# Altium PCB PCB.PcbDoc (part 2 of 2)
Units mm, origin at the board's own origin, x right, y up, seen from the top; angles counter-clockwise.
Board outline 43.18 x 17.78 mm, 4 copper layers (TOP, GND, SIG, BOTTOM), stack 1.586 mm thick; 72 components, 65 nets, 299 pads, 183 vias.
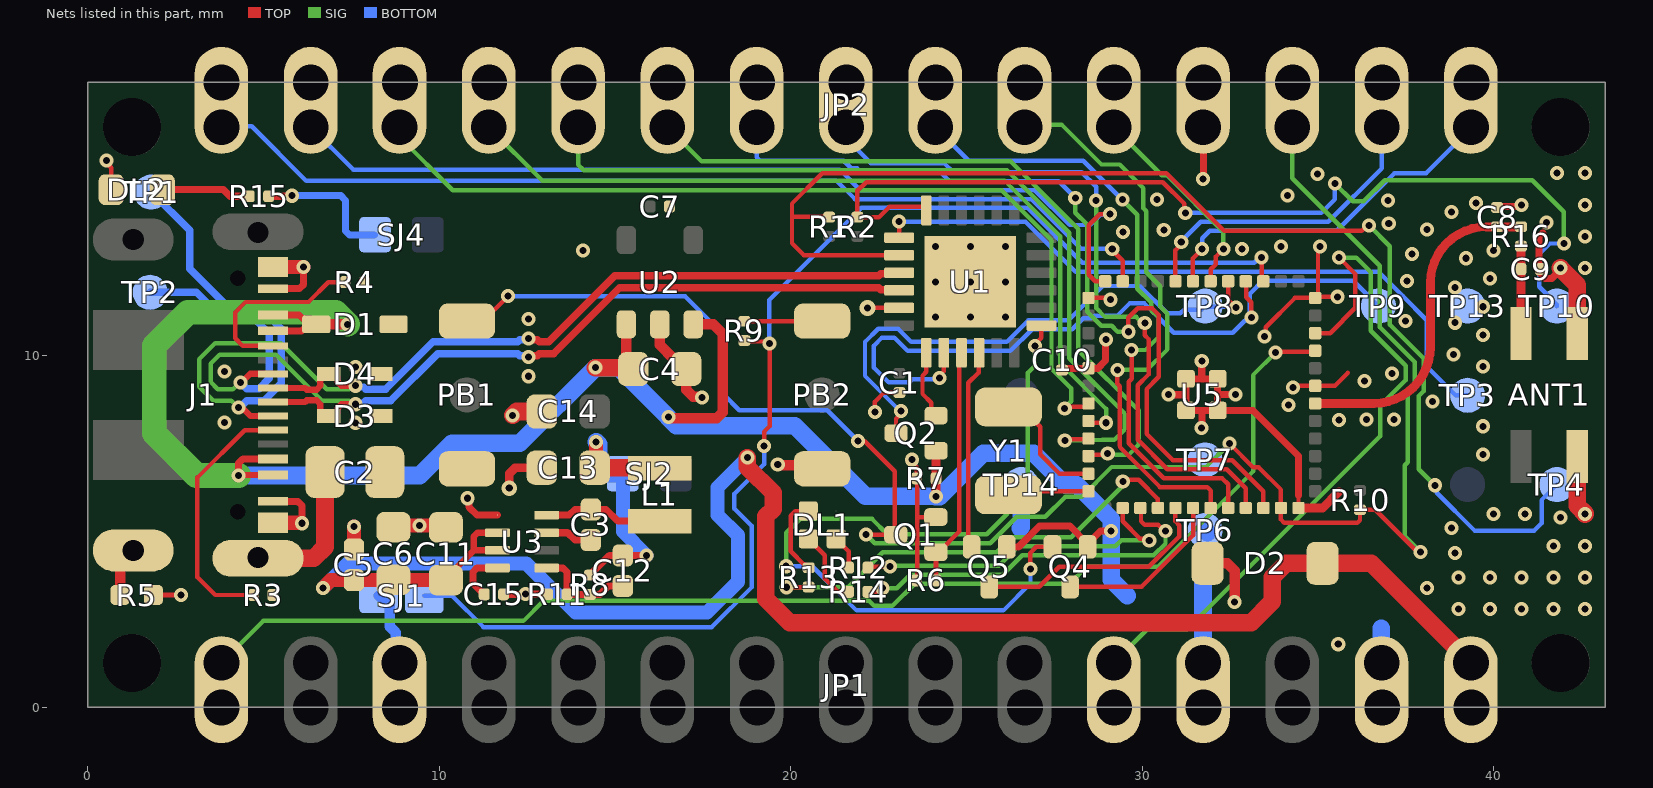
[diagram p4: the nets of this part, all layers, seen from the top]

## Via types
v1: diameter 0.4, hole 0.2, TOP to BOTTOM, tented both sides, 172 vias
v2: diameter 0.45, hole 0.2, TOP to BOTTOM, tented both sides, 11 vias

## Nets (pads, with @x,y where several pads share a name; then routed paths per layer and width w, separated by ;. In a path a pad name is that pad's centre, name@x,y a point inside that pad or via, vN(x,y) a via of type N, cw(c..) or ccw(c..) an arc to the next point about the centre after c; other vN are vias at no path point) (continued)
A7: JP1.11 U5.10 | length 19.8
  TOP w0.127: U5.10@34.925,10.65 35.35,10.65 36.068,11.368 36.068,12.332 v1(35.6,12.8)
  SIG w0.127: JP1.11@29.195,1.27 30.151,2.226 31.279,2.226 36.776,7.723 36.776,8.59 37.501,9.314 37.501,9.724 36.507,10.717 36.507,12.388 36.095,12.8 v1(35.6,12.8)
AREF_5: JP1.3 SJ1.1 | length 2.2
  BOTTOM w0.3: SJ1.1@8.28,3.182 8.598,2.864 8.598,2.305 8.77,2.132 8.77,1.375 JP1.3@8.875,1.27
CC1_3: J1.A5 R4.2 | length 5.4
  TOP w0.127: J1.A5@5.276,10.29 4.41,10.29 4.2,10.5 4.2,11.238 4.497,11.535 6.288,11.535 6.853,12.1 R4.2@7.333,12.1
CC2_3: J1.B5 R3.2 | length 7.4
  TOP w0.127: R3.2@4.725,3.2 3.635,3.2 3.126,3.709 3.126,6.545 4.472,7.89 J1.B5@5.276,7.89
CLK: JP1.1 U5.9 | length 36.5
  TOP w0.127: v1(33.8,10.1) 33.825,10.125 34.9,10.125 U5.9@34.925,10.15
  SIG w0.127: JP1.1@3.81,1.27 5.003,2.463 12.401,2.463 12.968,3.03 22.24,3.03 22.382,2.888 22.897,2.888 23.533,3.524 27.946,3.524 28.432,4.009 30.453,4.009 33.157,6.714 33.157,9.457 v1(33.8,10.1)
D2_SWV: JP2.5 U5.18 | length 5.9
  TOP w0.127: U5.18@31.953,12.127 31.953,12.463 32.102,12.612 32.102,12.83 32.312,13.04 v1(32.312,13.044)
  SIG w0.127: JP2.5@29.195,16.51 30.563,15.142 30.708,15.142 32.312,13.538 v1(32.312,13.044)
D3: JP2.6 U5.43 | length 16.5
  TOP w0.127: v1(29.3,9.605) 29.3,9.208 29.366,9.143 29.366,7.441 29.373,7.434 29.373,7.406 30.508,6.27 31.852,6.27 31.95,6.172 U5.43@31.95,5.675
  SIG w0.127: JP2.6@26.655,16.51 26.719,16.573 27.72,16.573 28.846,15.447 29.364,15.447 30.04,14.771 30.04,14.202 30.121,14.121 30.121,12.379 30.515,11.985 30.515,11.408 30.722,11.202 30.722,10.186 30.14,9.605 v1(29.3,9.605)
D4: JP2.7 U5.44 | length 18.1
  TOP w0.127: v1(29.705,10.17) 29.705,9.352 29.622,9.269 29.622,7.516 30.613,6.524 31.841,6.524 32.276,6.524 32.45,6.35 U5.44@32.45,5.675
  SIG w0.127: v1(29.437,14.445) 29.867,14.016 29.867,11.916 30.261,11.522 30.261,11.303 30.468,11.096 30.468,10.54 30.098,10.17 v1(29.705,10.17)
  BOTTOM w0.127: JP2.7@24.115,16.51 25.068,15.557 28.325,15.557 v1(29.437,14.445)
D5: JP2.8 U5.45 | length 20.7
  TOP w0.127: v1(30.077,10.935) 30.077,10.588 30.184,10.481 30.184,9.473 29.876,9.164 29.876,7.621 30.719,6.778 32.411,6.778 32.95,6.239 U5.45@32.95,5.675
  SIG w0.127: v1(28.693,14.418) 28.692,13.845 28.694,13.844 28.694,11.363 28.946,11.111 29.829,11.111 30.005,10.935 v1(30.077,10.935)
  BOTTOM w0.127: JP2.8@21.575,16.51 21.575,16.195 22.282,15.488 24.364,15.488 24.625,15.227 28.278,15.227 28.693,14.812 v1(28.693,14.418)
D6: JP2.9 U5.46 | length 24.6
  TOP w0.127: v1(29.611,10.689) 29.611,11.09 29.879,11.358 30.284,11.358 30.476,11.166 30.476,9.405 30.13,9.059 30.13,7.781 30.879,7.032 32.566,7.032 33.45,6.148 U5.46@33.45,5.675
  SIG w0.127: v1(28.1,14.5) 28.101,14.077 28.44,13.739 28.44,11.258 28.841,10.857 29.134,10.857 29.302,10.689 v1(29.611,10.689)
  BOTTOM w0.127: JP2.9@19.035,16.51 19.035,15.648 19.126,15.557 21.507,15.557 21.723,15.342 21.891,15.342 21.999,15.234 24.259,15.234 24.52,14.973 27.627,14.973 v1(28.1,14.5)
D7: JP2.10 U5.34 | length 21.3
  TOP w0.127: U5.34@28.475,7.15 28.516,7.19 28.983,7.19 v1(29.023,7.231)
  SIG w0.127: JP2.10@16.495,16.51 17.471,15.534 26.263,15.534 28.186,13.611 28.186,10.167 29.9,8.452 29.9,7.472 29.613,7.186 29.069,7.186 v1(29.023,7.231)
D8: JP2.11 U5.33 | length 24.7
  TOP w0.127: v1(27.801,7.601) 27.826,7.626 28.4,7.626 28.425,7.6 U5.33@28.475,7.65
  SIG w0.127: JP2.11@13.955,16.51 13.955,15.439 14.114,15.28 26.158,15.28 27.932,13.506 27.932,9.937 29.5,8.368 29.5,7.9 29.21,7.61 29.199,7.61 29.187,7.622 28.864,7.622 28.851,7.61 28.573,7.61 28.563,7.6 27.802,7.6 v1(27.801,7.601)
D_N: D4.2 J1.A7 J1.B7 TP1.X U1.21 | length 37.2
  TOP w0.18: v1@4.35,8.587 4.647,8.29 J1.A7@5.276,8.29 ; J1.B7@5.276,9.09 6.186,9.09 6.233,9.043 6.517,9.043 6.623,9.149 6.623,9.38 6.733,9.49 D4.2@6.868,9.49 7.003,9.49 7.113,9.38 7.113,9.259 7.218,9.153 v1(7.618,9.153)
  TOP w0.213: v1(12.545,10.502) 12.581,10.466 12.788,10.466 12.846,10.408 13.116,10.408 14.994,12.286 22.504,12.286 22.563,12.345 23.067,12.345 U1.21@23.088,12.366
  SIG w0.127: v1(4.3,8.537) 4.284,8.537 4.089,8.731 3.573,8.731 3.176,9.129 3.176,9.913 3.628,10.365 5.493,10.365 6.806,9.052 7.443,9.052 7.544,9.153 v1(7.618,9.153)
  BOTTOM w0.213: TP1.X@1.821,14.66 2.904,13.577 2.904,12.487 3.951,11.44 4.851,11.44 5.511,10.78 5.511,9.22 5.021,8.73 4.529,8.73 4.335,8.537 v1@4.311,8.537 ; v1(7.618,9.153) 7.654,9.118 7.861,9.118 7.919,9.06 8.48,9.06 9.828,10.408 12.245,10.408 12.303,10.466 12.509,10.466 v1(12.545,10.502)
D_P: D3.2 J1.A6 J1.B6 TP2.X U1.22 | length 33.4
  TOP w0.18: v1(4.349,9.25) 4.386,9.25 4.627,9.49 J1.A6@5.276,9.49 ; J1.B6@5.276,8.69 6.186,8.69 6.233,8.737 6.517,8.737 6.623,8.631 6.623,8.4 6.733,8.29 D3.2@6.868,8.29 7.003,8.29 7.113,8.4 7.113,8.521 7.218,8.627 v1(7.618,8.627)
  TOP w0.213: v1(12.545,9.975) 12.581,10.011 12.788,10.011 12.846,10.069 13.257,10.069 15.135,11.946 22.504,11.946 22.563,11.887 23.067,11.887 U1.22@23.088,11.866
  SIG w0.127: v1(4.349,9.25) 4.333,9.25 4.138,9.055 3.708,9.055 3.5,9.263 3.5,9.778 3.763,10.041 5.359,10.041 6.672,8.728 7.443,8.728 7.544,8.627 v1(7.618,8.627)
  BOTTOM w0.213: TP2.X@1.789,11.811 3.1,11.811 3.811,11.1 4.711,11.1 5.171,10.64 5.171,9.36 4.88,9.07 4.529,9.07 v1(4.349,9.25) ; v1(7.618,8.627) 7.654,8.662 7.861,8.662 7.919,8.72 8.62,8.72 9.969,10.069 12.245,10.069 12.303,10.011 12.509,10.011 v1(12.545,9.975)
GND: ANT1.3 ANT1.4 C1.1 C2.1 C4.1 C5.2 C6.1 C7.1 C8.2 C9.2 C10.1 C11.1 C13.1 C14.1 C15.1 D1.2 D3.1 D4.1 DL2.C J1.A1 J1.A12 J1.B1 J1.B12 JP1.14 JP2.4 PB1.1 PB2.1 Q1.S R3.1 R4.1 R5.1 R6.2 R7.2 R11.1 TP13.X TP14.X U1.23 U1.EXP U2.2 U3.1 U5.7 U5.12 U5.25 U5.29 U5.48 U5.49 U5.50 U5.51 U5.52 | length 54.7
  TOP w0.127: v1(0.544,15.563) 0.544,15.49 0.675,15.359 DL2.C@0.675,14.73 ; v2(22.193,11.366) U1.23@23.088,11.366 ; v1(22.4,8.4) 22.4,8.7 22.66,8.96 C1.1@23.097,8.96 ; v1(23.452,7.049) 23.452,6.975 23.588,6.839 R7.2@23.588,6.518 23.601,6.505 23.601,5.418 ; R6.2@23.588,3.618 23.601,3.631 23.601,5.418 ; Q1.S@24.133,5.418 23.601,5.418 ; U5.25@28.475,11.65 29.05,11.65 v1(29.1,11.6) ; v1@33.411,10.551 v1(33.485,10.551) ; v1@33.517,10.583 33.517,10.817 34.35,11.65 U5.12@34.925,11.65 U5.12@34.959,11.684 ; v1(34.3,9.1) 34.35,9.15 U5.7@34.925,9.15 35.489,9.15 35.856,9.517 ; U5.48@34.45,5.675 34.45,6.028 ; v1(35.057,13.111) 35.005,13.059 35.005,11.73 U5.12@34.959,11.684 ; v1(35.56,11.684) U5.12@34.959,11.684 ; v1@40.75,14.25 v1@40.8,14.2
  TOP w0.15: R5.1@1.875,3.2 1.877,3.198 2.663,3.198 v1(2.664,3.197)
  TOP w0.2: J1.B1@5.276,5.865 5.981,5.865 6.098,5.748 v1(6.098,5.241) ; J1.B12@5.276,11.915 6.033,11.915 6.15,12.032 v1(6.15,12.53) ; v1(10.811,5.952) 10.85,5.914 10.85,5.698 11.076,5.471 U3.1@11.663,5.471 ; C15.1@11.835,3.22 12.444,3.22 v1(12.459,3.234) 13.075,3.234 R11.1@13.088,3.221 ; C10.1@27.725,9.6 27.775,9.65 U5.29@28.475,9.65 28.742,9.65 28.958,9.866 28.958,10.451 v1(28.972,10.466)
  TOP w0.203: U1.EXP@24.396,11.385 v2(25.121,12.11) ; v1(30.748,8.899) 31.249,8.899 ; v1(31.69,7.952) 31.701,7.963 31.701,8.449 ; v1(31.699,9.852) 31.699,9.351 31.7,9.35 ; JP2.4@31.735,16.51 31.749,16.496 31.749,15.052 v1(31.738,15.041) ; 32.151,8.901 v1(32.652,8.901) ; 34.45,6.028 34.45,7.154 33.154,8.45 U5.49@32.15,8.45 ; C8.2@40.2,14.25 v1@40.75,14.25 ; 41.4,13.5 41.296,13.396 41.296,12.506 41.297,12.505 41.297,12.371 41.468,12.2 41.658,12.2 41.908,12.45 v1@41.95,12.45 ; 31.7,9.35 U5.52@32.15,9.35 U5.49@32.15,8.45 ; 31.7,9.35 U5.51@31.25,9.35 U5.50@31.25,8.45 U5.49@32.15,8.45
  TOP w0.25: U5.48@34.45,5.675 35.139,5.675 35.6,6.136
  TOP w0.254: v2(11.997,6.239) 11.997,6.653 12.166,6.821 C13.1@12.928,6.821
  TOP w0.3: U2.2@16.28,10.9 16.28,10.314 16.679,9.915 16.75,9.915 17.03,9.635 17.03,9.039 17.231,8.838 17.462,8.838 v1(17.481,8.819) ; v1(19.636,6.914) 19.655,6.895 20.795,6.895 PB2.1@20.9,6.79
  TOP w0.356: v1@6.072,5.255 6.086,5.241 v1(6.098,5.241)
  TOP w0.4: J1.A12@5.276,5.255 v1@6.072,5.255 ; J1.A1@5.28,12.53 v1(6.15,12.53) ; C5.2@7.58,4.542 v1(7.58,5.142) ; C6.1@8.935,5.182 C11.1@10.066,5.182
  TOP w0.5: v1(12.095,8.311) 12.206,8.421 C14.1@12.928,8.421
  TOP w0.508: J1.A1@5.276,12.525 J1.A1@5.28,12.53 ; v1(41.9,12.5) 41.95,12.45 42.38,12.02 ANT1.4@42.38,10.64 ; ANT1.3@42.38,7.14 42.38,5.739 42.6,5.519 v1(42.6,5.5)
  BOTTOM w0.5: 25.625,6.2 25.766,6.341 TP14.X@26.563,6.341 26.563,5.125 26.538,5.1 ; 36.8,2.25 36.8,1.27 JP1.14@36.815,1.27
  other v1: 35.581,1.8 39,2.8 39.9,2.8 40.8,2.8 41.7,2.8 42.6,2.8 38.1,3.4 39,3.7 39.9,3.7 40.8,3.7 41.7,3.7 42.6,3.7 38.9,4.4 41.7,4.6 42.6,4.6 38.8,5.1 9.443,5.182 41.9,5.4 40,5.5 40.9,5.5 39.7,7.2 39.7,8 3.894,8.107 7.618,8.1 35.605,8.184 36.386,8.189 37.167,8.189 34.163,8.607 38.26,8.7 36.331,9.289 12.545,9.423 37.11,9.5 3.894,9.555 7.618,9.68 39.7,9.7 38.86,10.046 39.7,10.6 38.9,10.946 37.499,10.999 12.545,11.055 39.7,11.4 38.9,11.946 37.536,12.136 39.9,12.2 42.6,12.5 39.22,12.78 37.68,12.9 14.1,13 40,13 32.847,13.044 33.947,13.114 42.6,13.4 29.452,13.521 30.618,13.586 38.105,13.595 37.018,13.77 41.5,13.8 38.8,14.1 40.8,14.3 42.6,14.3 39.5,14.35 37,14.421 30.431,14.454 34.134,14.559 34.994,15.179 41.8,15.2 42.6,15.2
  other v2: 24.121,11.11 25.121,11.11 26.121,11.11 24.121,12.11 26.121,12.11 24.121,13.11 25.121,13.11 26.121,13.11
MGM_AREF: R9.2 SJ1.2 U5.15 | length 36.2
  TOP w0.127: R9.2@18.687,10.437 18.712,10.411 19.275,10.411 19.33,10.356 v1(19.404,10.356) 19.404,8.002 19.246,7.844 v1(19.246,7.438) ; v1(33.4,12.8) 33.4,12.175 U5.15@33.45,12.125
  BOTTOM w0.127: SJ1.2@9.58,3.182 10.37,3.182 11.264,2.288 17.762,2.288 18.891,3.416 18.891,5.167 18.404,5.654 18.404,6.08 19.246,6.923 v1(19.246,7.438) ; v1(19.404,10.356) 19.392,10.368 19.392,11.592 22.011,14.211 26.739,14.211 28.297,12.653 33.189,12.653 33.336,12.8 v1(33.4,12.8)
MGM_RESET_CTL_4: Q1.G R6.1 U1.3 | length 6.8
  TOP w0.127: Q1.G@24.133,4.418 24.213,4.418 24.806,5.011 24.806,10.034 U1.3@24.863,10.091
  TOP w0.15: Q1.G@24.133,4.418 24.138,4.413 R6.1@24.138,3.618
MISO: JP2.15 U5.23 | length 27.8
  TOP w0.127: v1(29.152,13.048) 29.152,13.006 29.451,12.708 U5.23@29.451,12.126
  BOTTOM w0.127: JP2.15@3.81,16.51 3.833,16.533 4.672,16.533 6.225,14.98 21.317,14.98 21.833,14.465 26.844,14.465 28.26,13.048 v1(29.152,13.048)
MOSI: JP2.14 U5.24 | length 26.7
  TOP w0.127: U5.24@28.95,12.125 28.671,12.125 28.481,12.314 28.481,13.717 28.796,14.032 29.071,14.032 v1(29.083,14.044)
  BOTTOM w0.127: JP2.14@6.35,16.51 7.557,15.303 21.402,15.303 21.987,14.719 26.949,14.719 27.942,13.726 28.527,13.726 28.815,14.014 29.052,14.014 v1(29.083,14.044)
NetANT1_1: ANT1.1 C9.1 R16.2 | length 2.5
  TOP w0.254: ANT1.1@40.78,10.64 R16.2@40.78,13.105
NetC2_2: C2.2 J1.SHIELD2 | length 4.4
  TOP w0.508: J1.SHIELD2@4.929,4.349 J1.SHIELD2@4.851,4.27 4.876,4.245 6.435,4.245 6.758,4.568 6.758,6.797 C2.2@6.75,6.805
NetC3_1: C3.1 L1.1 U3.8 | length 3.4
  TOP w0.2: U3.8@13.063,5.471 13.699,5.471 13.863,5.635 C3.1@14.318,5.635 14.753,5.635 15.086,5.302 L1.1@16.28,5.302
NetC3_2: C3.2 U3.7 | length 1.3
  TOP w0.2: U3.7@13.063,4.971 13.66,4.971 13.867,4.765 C3.2@14.318,4.765
NetC8_1: C8.1 R16.1 U5.6 | length 9.5
  TOP w0.254: U5.6@34.925,8.65 36.593,8.65 36.594,8.65 ccw(c36.594,10.256) 38.2,10.256 38.2,12.08 cw(c39.795,12.08) 39.795,13.675 R16.1@40.8,13.675
NetC12_1: C12.1 R8.1 R11.2 U3.5 | length 3
  TOP w0.2: U3.5@13.063,3.971 13.521,3.971 13.638,3.854 R11.2@13.638,3.221 14.291,3.221 R8.1@14.297,3.215 ; R8.1@14.322,3.191 R8.1@14.297,3.215 ; C12.1@15.23,3.455 14.813,3.455 14.574,3.215 R8.1@14.297,3.215
NetC12_2: C12.2 C13.2 L1.2 R8.2 SJ2.1 | length 8.5
  TOP w0.2: R8.2@14.297,3.779 14.325,3.779 14.367,3.82 14.367,3.849 14.843,4.325 C12.2@15.23,4.325 v1(15.906,4.325)
  TOP w0.4: C13.2@14.428,6.821 14.468,6.861 v1(14.468,7.553)
  TOP w0.5: C13.2@14.428,6.821 16.26,6.821 L1.2@16.28,6.802
  BOTTOM w0.4: SJ2.1@15.23,6.652 15.23,5.002 v1(15.906,4.325)
  BOTTOM w0.5: v1(14.468,7.553) 14.539,7.483 14.539,6.944 14.832,6.652 SJ2.1@15.23,6.652
NetC15_2: C15.2 U3.4 | length 1.5
  TOP w0.2: C15.2@11.284,3.22 11.284,3.235 11.229,3.29 11.21,3.29 10.967,3.533 10.967,3.858 11.084,3.975 U3.4@11.659,3.975
NetDL1_1: DL1.1 R13.1 | length 2.3
  TOP w0.127: DL1.1@20.505,5.589 20.137,5.589 20.007,5.459 20.007,4.441 20.392,4.056 20.434,4.056 R13.1@20.515,3.975
NetDL1_2: DL1.2 R14.1 | length 2.2
  TOP w0.127: DL1.2@20.505,4.799 20.971,4.333 20.971,3.668 21.35,3.29 R14.1@21.65,3.29
NetDL1_3: DL1.3 R12.1 | length 1
  TOP w0.127: DL1.3@21.295,4.799 21.65,4.444 R12.1@21.65,3.98
NetDL2_A: DL2.A R15.1 | length 2.6
  TOP w0.2: DL2.A@2.125,14.73 3.87,14.73 4.056,14.544 R15.1@4.602,14.544
NetJ1_SHIELD4: J1.SHIELD4 R5.2 | length 1.4
  TOP w0.3: R5.2@0.925,3.2 0.925,4.094 J1.SHIELD4@1.301,4.47
NetPB2_2: PB2.2 R9.1 | length 2.2
  TOP w0.127: R9.1@18.687,10.987 20.897,10.987 PB2.2@20.9,10.99
NetR15_2: R15.2 SJ4.2 | length 4
  TOP w0.2: R15.2@5.152,14.544 5.796,14.544 v1(5.811,14.559)
  BOTTOM w0.2: v1(5.811,14.559) 7.208,14.559 7.341,14.426 7.341,13.556 7.458,13.439 SJ4.2@8.169,13.439
NetU5_35: U5.35 Y1.2 | length 3.6
  TOP w0.127: Y1.2@26.2,8.55 26.626,8.55 26.626,8.463 27.1,7.989 27.1,7.2 27.65,6.65 U5.35@28.475,6.65
NetU5_36: U5.36 Y1.1 | length 2.3
  TOP w0.127: Y1.1@26.2,6.05 26.3,6.15 U5.36@28.475,6.15
PTI_DATA: JP2.12 U5.32 | length 23.9
  TOP w0.127: U5.32@28.475,8.15 28.525,8.1 v1(28.975,8.1)
  SIG w0.127: JP2.12@11.415,16.51 12.935,14.99 26.089,14.99 27.678,13.401 27.678,9.79 28.975,8.493 v1(28.975,8.1)
PTI_SYNC: JP2.13 U5.31 | length 25.9
  TOP w0.127: v1(27.8,8.5) 27.862,8.562 28.387,8.562 U5.31@28.475,8.65
  SIG w0.127: JP2.13@8.875,16.51 8.875,16.23 10.39,14.716 26.004,14.716 27.424,13.296 27.424,9.636 27.984,9.077 27.984,8.711 27.8,8.527 v1(27.8,8.5)
R\E\S\E\T\: JP2.3 PB1.2 Q1.D R10.1 TP7.X U5.47 | length 52.2
  TOP w0.127: PB1.2@10.794,10.99 11.119,11.314 11.576,11.314 v1(11.962,11.7) ; v1(21.922,7.577) 22.113,7.577 22.967,6.723 22.967,4.944 Q1.D@22.993,4.918 22.146,4.918 v1(22.142,4.922) ; v1(32.485,7.509) 33.165,6.828 33.322,6.828 33.95,6.2 U5.47@33.95,5.675 33.95,5.348 34.048,5.25 36.126,5.25 36.2,5.324 R10.1@36.2,5.625 36.631,5.625 37.712,4.544 37.718,4.544 37.838,4.423 v1(37.926,4.423)
  SIG w0.127: v1(22.142,4.922) 22.393,4.671 25.68,4.671 26.431,5.422 27.25,5.422 27.818,5.99 28.28,5.99 29.131,6.841 31.818,6.841 v1@32.479,7.502 ; JP2.3@34.275,16.51 34.275,15.052 36.761,12.566 36.761,10.822 37.755,9.829 37.755,9.189 37.557,8.992 37.557,6.976 37.473,6.892 37.473,4.876 v1(37.926,4.423)
  BOTTOM w0.127: v1(11.962,11.7) 17,11.7 18.105,10.595 18.105,8.894 18.542,8.456 21.043,8.456 v1(21.922,7.577) ; TP7.X@31.795,7.041 32.017,7.041 v1(32.485,7.509)
RGB_B: R13.2 U5.40 | length 13
  TOP w0.127: v1(19.879,3.421) 19.882,3.423 20.513,3.423 R13.2@20.515,3.425 ; v1(29.451,6.43) 29.498,6.477 29.905,6.477 30.45,5.932 U5.40@30.45,5.675
  SIG w0.127: v1(19.879,3.421) 19.885,3.416 21.624,3.416 22.626,4.417 25.868,4.417 26.291,4.84 27.985,4.84 29.451,6.306 v1(29.451,6.43)
RGB_G: R14.2 U5.39 | length 10.6
  TOP w0.127: R14.2@22.2,3.29 22.437,3.29 22.541,3.393 v1(22.615,3.393) ; U5.39@29.95,5.675 29.97,5.656 29.97,5.299 30.071,5.197 30.456,5.197 30.628,5.025 v1(30.667,5.025)
  SIG w0.127: v1(22.615,3.393) 23.022,3.393 23.407,3.778 26.036,3.778 26.59,4.332 30.336,4.332 30.667,4.662 v1(30.667,5.025)
RGB_R: R12.2 U5.38 | length 9.7
  TOP w0.127: R12.2@22.2,3.98 22.218,3.997 22.814,3.997 v1(22.831,4.015) ; U5.38@29.45,5.675 29.45,5.295 29.94,4.805 30.152,4.805 v1(30.205,4.752)
  SIG w0.127: v1(22.831,4.015) 22.848,4.032 25.93,4.032 26.485,4.586 29.238,4.586 29.405,4.752 v1(30.205,4.752)
SAMD11_N_RESET_4: R2.2 TP10.X U1.18 | length 28.4
  TOP w0.127: U1.18@23.863,14.141 23.863,14.154 23.777,14.24 22.805,14.24 22.514,13.95 R2.2@21.9,13.95 21.9,14.696 22.15,14.946 30.588,14.946 31.198,14.336 31.198,14.099 v1(31.229,14.068)
  SIG w0.127: v1(35.488,14.903) 35.991,14.4 36.3,14.4 36.9,15 41.1,15 42,14.1 v1(42,13.2)
  BOTTOM w0.127: v1(31.229,14.068) 35.097,14.068 35.488,14.459 v1(35.488,14.903) ; TP10.X@41.803,11.421 41.803,11.464 41.3,11.967 41.3,12.9 41.6,13.2 v1(42,13.2)
SAMD11_PA02_4: Q2.S U1.1 | length 2
  TOP w0.127: U1.1@23.863,10.091 23.863,9.549 23.753,9.439 23.753,8.92 24.002,8.671 24.002,8.44 Q2.S@24.137,8.305
SAMD11_PA05_4: Q5.S U1.4 | length 5.7
  TOP w0.127: Q5.S@25.152,4.571 25.06,4.664 25.06,9.237 25.351,9.529 25.351,10.079 U1.4@25.363,10.091
SAMD11_PA08_4: Q4.S U1.7 | length 22.9
  TOP w0.127: v1(26.826,3.941) 26.815,3.953 26.815,4.395 26.991,4.571 Q4.S@27.452,4.571 ; v1(26.953,10.282) 26.953,10.336 27.138,10.521 U1.7@27.138,10.866
  SIG w0.127: v1(19.877,4.019) 19.877,4.969 20.272,5.364 22.319,5.364 22.755,4.929 25.579,4.929 26.754,6.104 26.754,9.525 26.953,9.723 v1(26.953,10.282)
  BOTTOM w0.127: v1@19.877,4.019 20.62,4.019 21.878,2.762 26.055,2.762 26.826,3.532 v1(26.826,3.941)
SAMD11_RX: Q5.D U5.41 | length 6.9
  TOP w0.127: Q5.D@25.652,3.431 27.073,3.431 27.642,4 30.194,4 31.057,4.863 31.057,5.186 30.95,5.294 U5.41@30.95,5.675
SAMD11_SWCLK_4: TP3.X U1.19 | length 19.4
  TOP w0.127: U1.19@23.088,13.366 23.091,13.369 v1(23.091,13.82)
  BOTTOM w0.127: v1(23.091,13.82) 26.684,13.82 28.113,12.391 36.73,12.391 37.414,11.707 ; 37.414,11.707 38.1,11.02 38.1,9.7 38.919,8.881 TP3.X@39.263,8.881
SAMD11_SWDIO_4: R1.1 TP4.X U1.20 | length 36.2
  TOP w0.127: R1.1@21.1,13.95 21.088,13.962 20.042,13.962 ; U1.20@23.088,12.866 20.381,12.866 20.042,13.205 20.042,13.962 ; v1(36.457,13.715) 36.403,13.715 36.246,13.558 32.335,13.558 30.694,15.2 20.906,15.2 20.042,14.336 20.042,13.962
  SIG w0.127: v1@36.474,13.698 37.049,13.123 37.049,10.894 38.009,9.934 38.009,9.001 37.87,8.862 37.87,6.78 v1(38.329,6.322)
  BOTTOM w0.127: v1(38.329,6.322) 38.381,6.269 38.381,6.112 39.459,5.033 41.157,5.033 41.364,5.241 41.364,5.902 TP4.X@41.803,6.341
SAMD11_TX: Q4.D U5.42 | length 4.9
  TOP w0.127: Q4.D@27.952,3.431 29.985,3.431 31.45,4.896 U5.42@31.45,5.675
SWCLK: TP9.X U1.2 U5.16 | length 21.4
  TOP w0.127: v1(24.24,9.374) 24.24,9.447 24.363,9.571 U1.2@24.363,10.091 ; U5.16@32.95,12.125 32.967,12.107 32.967,11.67 33.11,11.527 33.11,11.107 v1(33.117,11.099)
  BOTTOM w0.127: v1(24.24,9.374) 24.199,9.333 23.463,9.333 23.378,9.248 22.787,9.248 22.372,9.664 22.372,10.294 22.6,10.523 22.952,10.523 23.329,10.146 26.257,10.146 26.873,10.762 28.015,10.762 28.325,11.072 28.572,11.072 28.65,11.15 29.299,11.15 29.643,11.495 30.069,11.495 30.901,10.663 32.582,10.663 32.92,11.001 32.949,11.001 v1@33.046,11.099 ; v1(33.117,11.099) 33.069,11.147 33.069,11.769 33.437,12.137 36.007,12.137 TP9.X@36.723,11.421
SWDIO: Q2.D TP8.X U5.17 | length 15.8
  TOP w0.127: Q2.D@23,7.805 23,8.217 23.145,8.362 v1(23.145,8.436) ; U5.17@32.45,12.125 32.45,11.595 v1(32.669,11.376)
  BOTTOM w0.127: v1(23.145,8.436) 23.114,8.436 22.118,9.432 22.118,10.399 22.495,10.777 23.057,10.777 23.434,10.4 26.151,10.4 26.768,11.016 27.91,11.016 28.884,11.99 29.939,11.99 30.715,11.215 31.089,11.215 31.195,11.321 31.695,11.321 TP8.X@31.795,11.421 ; TP8.X@31.834,11.382 31.85,11.398 32.646,11.398 v1(32.669,11.376)
UART0_RX: JP2.2 U5.20 | length 8.9
  TOP w0.127: U5.20@30.945,12.129 30.945,13.002 31.115,13.172 v1(31.115,13.246)
  BOTTOM w0.127: v1(31.115,13.246) 31.115,13.264 31.666,13.814 35.294,13.814 36.815,15.335 JP2.2@36.815,16.51
UART0_TX: JP2.1 U5.19 | length 10.3
  TOP w0.127: U5.19@31.443,12.132 31.443,12.773 31.711,13.04 v1(31.711,13.044)
  BOTTOM w0.127: v1(31.711,13.044) 31.711,13.349 31.922,13.56 35.54,13.56 37.18,15.2 38.08,15.2 39.355,16.475 JP2.1@39.355,16.51
VIN: C5.1 C6.2 C11.2 D2.C JP1.15 U3.2 U3.3 | length 50.5
  TOP w0.18: C11.2@10.298,3.773 10.996,4.471 ; U3.3@11.663,4.471 10.996,4.471 ; U3.2@11.663,4.971 11.093,4.971 10.988,4.866 10.988,4.48 10.996,4.471
  TOP w0.4: v1(6.698,3.402) 6.919,3.622 7.49,3.622 7.54,3.672 C5.1@7.58,3.672 ; C5.1@7.587,3.629 C6.2@8.7,3.629 C11.2@10.188,3.629
  TOP w0.5: v1(18.774,7.106) 18.774,6.837 19.504,6.107 19.504,5.644 19.3,5.439 19.3,3.089 19.974,2.415 33.101,2.415 33.7,3.014 33.7,3.7 34.1,4.1 D2.C@35.135,4.1 36.525,4.1 JP1.15@39.355,1.27
  BOTTOM w0.4: v1(6.698,3.402) 7.392,4.096 12.481,4.096 13.877,2.7 17.622,2.7 18.5,3.578 18.5,4.9 17.922,5.478 17.922,6.254 v1(18.774,7.106)
VUSB: C4.2 D1.1 D2.A J1.A4 J1.A9 J1.B4 J1.B9 JP1.12 Q2.G Q4.G Q5.G R7.1 TP6.X U2.1 U2.3 | length 64.9
  TOP w0.18: v1@4.313,6.613 J1.A9@5.274,6.613
  TOP w0.2: v1(4.3,6.6) 4.3,6.948 4.417,7.065 J1.B4@5.276,7.065 ; J1.B9@5.276,10.715 6.091,10.715 6.126,10.75 6.358,10.75 D1.1@6.508,10.9 6.358,11.05 6.14,11.05 6.019,11.171 J1.A4@5.282,11.171 ; Q5.G@26.152,4.571 26.491,4.571 27.079,5.16 27.945,5.16 28.453,4.652 28.82,5.019 v1(29.12,5.02)
  TOP w0.25: v1(24.135,5.998) v1(24.135,5.998) 24.136,6.517 R7.1@24.138,6.518 ; R7.1@24.14,6.52 Q2.G@24.14,7.305
  TOP w0.254: v1(4.3,6.6) v1@4.313,6.613
  TOP w0.3: D1.1@6.508,10.9 v1(7.4,10.9) ; U2.1@15.33,10.9 15.33,9.824 15.405,9.749 C4.2@15.53,9.624 ; v1(16.531,8.258) 16.55,8.239 16.621,8.239 16.631,8.228 17.896,8.228 18.071,8.404 18.071,10.629 17.8,10.9 U2.3@17.23,10.9 ; R7.1@24.138,6.518 R7.1@24.14,6.52 ; D2.A@31.865,4.1 32.42,4.1 32.632,3.888 v1(32.632,3.002)
  TOP w0.5: v1(14.451,9.671) 15.345,9.671 15.405,9.731 C4.2@15.405,9.749
  SIG w0.508: JP1.12@31.735,1.27 JP1.12@31.97,1.27
  SIG w0.7: v1(4.3,6.6) 3.1,6.6 1.9,7.8 1.9,10.286 2.858,11.244 7.056,11.244 v1(7.4,10.9)
  BOTTOM w0.5: v1(4.3,6.6) 9.448,6.6 10.369,7.521 12.301,7.521 v1(14.451,9.671) 15.111,9.671 v1@16.524,8.258 ; v1@16.517,8.244 16.746,8.015 20.119,8.015 22.131,6.003 v1@24.129,6.003 ; v1(24.135,5.998) 24.249,5.998 25.487,7.236 26.917,7.236 27.818,6.336 28.143,6.336 29.12,5.359 v1(29.12,5.02) 29.12,3.636 29.579,3.177
  BOTTOM w0.508: JP1.12@31.735,1.27 31.735,3.49 ; TP6.X@31.795,5.041 TP6.X@31.86,4.976
pads on no net: ANT1.2 Fiducial_1.1 Fiducial_2.1 J1.A8 J1.B8 J1.FIXING J1.SHIELD1 J1.SHIELD3 JP1.13 U1.5 U1.6 U1.8 U1.9 U1.10 U1.11 U1.12 U1.13 U1.14 U1.15 U1.16 U1.17 U2.4 U3.6 U5.1 U5.2 U5.3 U5.4 U5.5 U5.26 U5.27

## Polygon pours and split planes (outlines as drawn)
GND on TOP "GND_L01_P008" (solid, remove dead copper, pour order 8): 0,17.78 43.18,17.78 43.18,0 0,0
+3V3 on TOP "+3V3_L01_P005" (solid, remove dead copper, pour order 5): 15.309,9.592 15.472,9.722 17.355,9.722 19.063,7.77 19.063,3.884 18.963,3.771 17.497,3.771 17.355,3.913 17.355,7.45 15.473,7.45 15.309,7.603
GND on BOTTOM "GND_L04_P009" (solid, remove dead copper, pour order 9): 0,17.78 43.18,17.78 43.18,0 0,0
VUSB on BOTTOM "VUSB_L04_P003" (solid, remove dead copper, pour order 3): 32.845,5.71 32.845,0 28.756,0 28.756,5.71
GND on GND "GND_L02_P001" (solid, remove dead copper, pour order 1): 0,17.78 43.18,17.78 43.18,0 0,0
GND on SIG "GND_L03_P002" (solid, remove dead copper, pour order 2): 0,17.78 43.18,17.78 43.18,0 0,0

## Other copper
TOP:
  pour cut-out: 11.022,5.177 12.322,5.177 12.322,5.99 11.022,5.99
  pour cut-out: 6.375,14.275 6.375,12.775 4.875,12.775 4.875,11.475 3.075,11.475 3.075,5.996 4.701,5.996 4.701,4.975 6.275,4.975 6.275,3.537 -0.025,3.537 -0.025,14.255
  region net NetANT1_1: 40.48,12.02 40.706,12.246 40.706,12.303 40.854,12.303 40.854,12.245 41.08,12.02
  pour cut-out: 35.1,3.8 36.825,3.8 39.355,1.27 34.275,1.27 34.275,2.975
  pour cut-out: 39.98,5.76 43.18,5.76 43.18,12.02 39.98,12.02
  pour cut-out: 27.8,8.7 27.488,9.012 24.05,9.012 24.05,6.15 24.9,5.3 27.252,5.3 27.8,5.848
  pour cut-out: 0,17.78 0,16.955 1.27,15.685 41.91,15.685 43.18,16.955 43.18,17.78
  pour cut-out: 0,0 0,0.826 1.27,2.096 41.91,2.096 43.18,0.826 43.18,0
GND:
  pour cut-out: 6.375,14.275 6.375,12.775 4.875,12.775 4.875,11.475 3.075,11.475 3.075,5.996 4.701,5.996 4.701,4.975 6.275,4.975 6.275,3.537 -0.025,3.537 -0.025,14.255
  pour cut-out: 39.98,5.76 43.18,5.76 43.18,12.02 39.98,12.02
SIG:
  pour cut-out: 6.375,14.275 6.375,12.775 4.875,12.775 4.875,11.475 3.075,11.475 3.075,5.996 4.701,5.996 4.701,4.975 6.275,4.975 6.275,3.537 -0.025,3.537 -0.025,14.255
  pour cut-out: 34.275,16.51 41.91,16.51 41.91,15.71 41,14.8 35.985,14.8
BOTTOM:
  pour cut-out: 6.375,14.275 6.375,12.775 4.875,12.775 4.875,11.475 3.075,11.475 3.075,5.996 4.701,5.996 4.701,4.975 6.275,4.975 6.275,3.537 -0.025,3.537 -0.025,14.255
  pour cut-out: 0,0 0,0.826 1.27,2.096 41.91,2.096 43.18,0.826 43.18,0
  pour cut-out: 0,17.78 0,16.955 1.27,15.685 41.91,15.685 43.18,16.955 43.18,17.78
  text ".Version" at 0.55,7.25 h0.8 r270

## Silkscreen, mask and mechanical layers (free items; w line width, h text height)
Route Tool Path:
  lines w2: -1,1 -1,0 ccw(c0,0) 0,-1 43.18,-1 ccw(c43.18,0) 44.18,0 44.18,6.5 ; -1,5 -1,13 ; -1,17 -1,17.78 cw(c0,17.78) 0,18.78 43.18,18.78 cw(c43.18,17.78) 44.18,17.78 44.18,10.5
Board:
  the board outline again, w0.1
NANO TP AND SIGNALS:
  drawing of 309 lines, arcs and shapes, not listed
  text "D12" at 3.435,15.14 h0.3
  text "D11" at 6.025,15.14 h0.3
  text "D10" at 8.515,15.14 h0.3
  text "D9" at 11.18,15.14 h0.3
  text "D9" at 11.18,15.14 h0.3
  text "D8" at 13.72,15.14 h0.3
  text "D7" at 16.26,15.14 h0.3
  text "D6" at 18.8,15.14 h0.3
  text "D5" at 21.325,15.14 h0.3
  text "D4" at 23.865,15.14 h0.3
  text "D3" at 26.42,15.14 h0.3
  text "D2" at 28.96,15.14 h0.3
  text "GND" at 31.35,15.14 h0.3
  text "NRST" at 33.74,15.14 h0.3
  text "D1" at 36.63,15.14 h0.3
  text "D0" at 39.12,15.14 h0.3
  text "RX" at 36.58,14.54 h0.3
  text "TX" at 39.12,14.54 h0.3
  text "USB DN" at 2.5,14.11 h0.3
  text "USB DP" at 2.5,11.261 h0.3
  text "GND" at 38.8,10.35 h0.3
  text "RESET" at 41.1,10.35 h0.3
  text "SWCLK" at 38.35,7.85 h0.3
  text "NC" at 41.55,7.85 h0.3
  text "VUSB" at 31.245,5.791 h0.3
  text "3V3" at 38.75,5.25 h0.3
  text "SWDIO" at 41.125,5.25 h0.3
  text "D13" at 3.435,3.02 h0.3
  text "VREF OR" at 7.89,3.02 h0.3
  text "VBUS" at 31.2,3.02 h0.3
  text "NRST OR" at 33.29,3.02 h0.3
  text "SCK" at 3.41,2.42 h0.3
  text "OTHER" at 8.19,2.42 h0.3
  text "5V" at 31.5,2.42 h0.3
  text "OTHER" at 33.59,2.42 h0.3
  text "3V3" at 5.95,2.32 h0.3
  text "A0" at 11.18,2.32 h0.3
  text "A0" at 11.18,2.32 h0.3
  text "A1" at 13.77,2.32 h0.3
  text "A2" at 16.26,2.32 h0.3
  text "A3" at 18.8,2.32 h0.3
  text "A6" at 26.42,2.32 h0.3
  text "A7" at 28.96,2.32 h0.3
  text "GND" at 36.43,2.32 h0.3
  text "VIN" at 38.995,2.32 h0.3
  text "A4" at 21.325,2.311 h0.3
  text "A5" at 23.865,2.311 h0.3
